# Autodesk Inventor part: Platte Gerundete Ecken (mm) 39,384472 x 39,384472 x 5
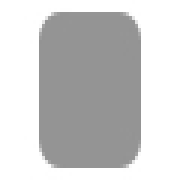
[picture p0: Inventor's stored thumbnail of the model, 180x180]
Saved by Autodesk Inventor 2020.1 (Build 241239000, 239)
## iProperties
Created: 2019-01
Part Number: Platte Gerundete Ecken (mm) 39,384472 x 39,384472 x 5
Material: Stahl, weich
Document SubType Name: Modeling
Designer: lutzd
Language: de-DE
Size Designation: 5 x 39,384472 x 39,384472
Categories: <MemberInstance><Categories><Category DisplayName="Sonstige Bauteile" InternalName="5aa15e00-363f-49f2-933f-16f664388e3f" Mnemonic="OTHER"><Category DisplayName
Mass: 60.0398 g
Surface Area: 38.0412 cm^2
Volume: 7.64838 cm^3
Density: 7.85 g/cm^3
Appearance: Halbpoliert
IsCustomPart: 1
Author: lutzd
Revision Number: -
Dimensions: 39,4x39,4x5 mm
Mass: 0,06 kg
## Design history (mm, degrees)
sketch "Sketch1"
  geometry: L1 (0, 20.175)-(0, -21.446); L2 (-20.203, 0)-(20.169, 0); L3 (-19.692, 19.692)-(19.692, 19.692); L4 (19.692, 19.692)-(19.692, -19.692); L5 (19.692, -19.692)-(-19.692, -19.692); L6 (-19.692, -19.692)-(-19.692, 19.692); 1 further point
  constraints: 12 end point, 2 horizontal, 2 parallel, 2 point on line, 1 perpendicular, 1 vertical
  dimensions: "d0" = 39.38447 distance between parallel lines of L5 L3 (= height); "d1" = 19.69224 distance between parallel lines of L2 L3 (= 0.5 x height); "d2" = 39.38447 distance between parallel lines of L6 L4 (= width); "d3" = 19.69224 distance between parallel lines of L6 L1 (= 0.5 x width)
extrude "Extrusion1" new body sketch "Sketch1" distance "d4" = 5 (= thickness); taper "d5" = 0 deg
fillet "Fillet1" dims "d6" = 5 (= fillet), "d7" = 0, "fillet" = 5 [user parameter; used in 1 equation term]
chamfer "Chamfer1" distance "d8" = 0 (computed from chamfer); stored, may be unused: second distance "d9" = 2, angle "d10" = 45 deg; dims "d11" = 0, "chamfer" = 0 [user parameter; used in 1 equation term]
body "Solid1"
other parameters: "thickness" = 5 [user parameter; used in 1 equation term], "width" = 39.38447 [user parameter; used in 2 equation terms], "height" = 39.38447 [user parameter; used in 2 equation terms]
